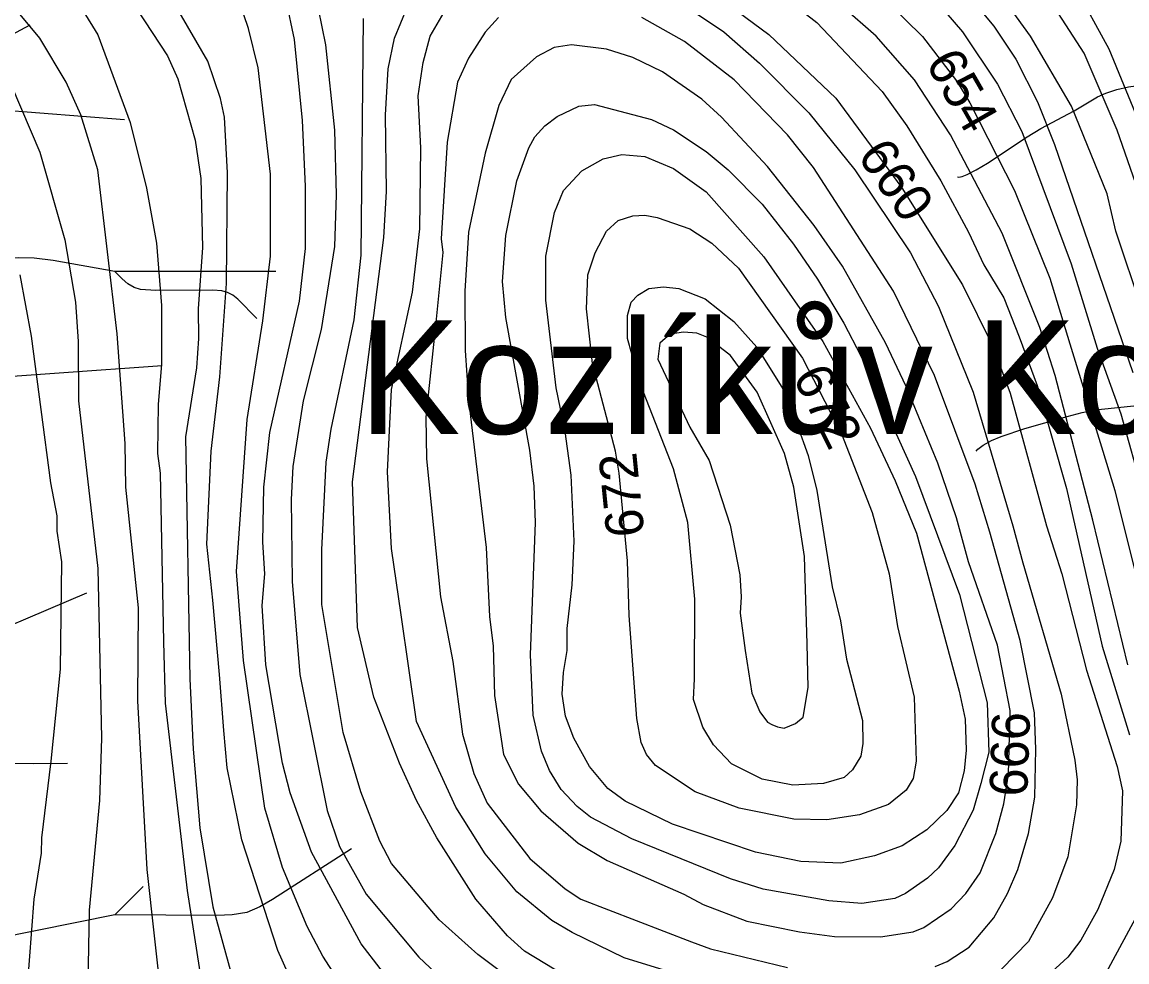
# Model space of a CAD drawing. Extents: x -709584 to -702006, y -1161789 to -1157496.
# Drawn here: x -708051.5 to -707759.7, y -1160434.4 to -1160186.2 of the extents above; entities that cross this region are included whole.
import ezdxf

# ---------------------------------------------------------------- set-up
doc = ezdxf.new("R2010")
doc.units = 0
for name, color, linetype in [('105_místní názvy', 7, 'Continuous'), ('120_vrstevnice hlavní', 7, 'Continuous'), ('121_vrstevnice hlavní_popis', 7, 'Continuous'), ('122_vrstevnice základní', 7, 'Continuous'), ('124_vrstevnice doplňková', 7, 'Continuous'), ('411_akumulovaný odtok', 7, 'Continuous')]:
    doc.layers.add(name, color=color, linetype=linetype)

msp = doc.modelspace()

# ---------------------------------------------------------------- linework, layer by layer
at = {"layer": '120_vrstevnice hlavní'}
for points in [[(-707866.46, -1160180.46), (-707854.31, -1160189.43), (-707836.58, -1160206.29), (-707819.17, -1160229.93), (-707803.11, -1160255.53), (-707795.3, -1160271.44), (-707790.53, -1160284.17), (-707780.98, -1160319.18), (-707776.93, -1160331.9), (-707770.42, -1160357.36), (-707762.32, -1160382.82), (-707760.87, -1160389.18), (-707761.31, -1160402.49), (-707763.04, -1160410.01), (-707767.38, -1160420.57), (-707771.87, -1160428.67), (-707775.34, -1160433.16), (-707782.71, -1160439.95)], [(-707801.66, -1160179.02), (-707794.87, -1160187.26), (-707789.08, -1160195.94), (-707783.29, -1160207.22), (-707778.81, -1160218.5), (-707758.13, -1160278.68)], [(-707968.58, -1160465.84), (-707983.92, -1160431.42), (-707993.46, -1160402.2), (-707997.37, -1160383.11), (-707998.23, -1160373.27), (-707999.39, -1160358.52), (-708001.13, -1160338.85), (-708002.72, -1160324.09), (-708001.56, -1160299.5), (-707999.25, -1160279.83), (-707997.51, -1160255.24), (-707997.22, -1160226.02), (-707998.09, -1160211.27), (-707999.1, -1160206.35), (-708002.43, -1160196.52), (-708010.96, -1160181.76)], [(-707908.12, -1160438.07), (-707918.83, -1160431.56), (-707923.31, -1160427.51), (-707931.7, -1160417.82), (-707941.97, -1160401.62), (-707947.32, -1160391.79), (-707951.81, -1160381.95), (-707958.6, -1160364.45), (-707962.89, -1160346.1), (-707964.24, -1160307.6), (-707956, -1160243.09), (-707955.28, -1160230.94), (-707955.57, -1160210.69), (-707954.84, -1160198.54), (-707953.11, -1160190.44), (-707949.78, -1160182.34)], [(-707887, -1160221.69), (-707879.48, -1160224.87), (-707870.85, -1160231.03), (-707855.62, -1160248.15), (-707840, -1160270.57), (-707827.41, -1160293.43), (-707820.9, -1160307.31), (-707815.26, -1160321.2), (-707803.98, -1160362.86), (-707802.4, -1160370.28), (-707802.21, -1160378.52), (-707802.73, -1160383.92), (-707804.23, -1160389.77), (-707807.26, -1160394.42), (-707812.55, -1160399.56), (-707819.1, -1160403.72), (-707826.41, -1160406.41), (-707835.24, -1160408.36), (-707845.82, -1160407.87), (-707857.79, -1160405.38), (-707879.77, -1160398.01), (-707892.21, -1160391.93), (-707896.84, -1160388.6), (-707901.61, -1160382.82), (-707905.81, -1160375.3), (-707907.98, -1160369.51), (-707908.84, -1160363.73), (-707908.56, -1160357.94), (-707907.54, -1160352.15), (-707907.54, -1160346.37), (-707906.24, -1160334.8), (-707905.66, -1160323.23), (-707906.53, -1160305.87), (-707908.12, -1160294.3), (-707910.44, -1160282.73), (-707913.19, -1160259.58), (-707913.19, -1160248.01), (-707910.87, -1160236.44), (-707908.56, -1160230.65), (-707903.64, -1160225.45), (-707898, -1160222.26), (-707893.08, -1160221.11), (-707887, -1160221.69)], [(-708054.79, -1160476.55), (-708050.16, -1160442.12), (-708048.28, -1160417.82), (-708046.4, -1160405.67), (-708046.26, -1160401.62), (-708043.8, -1160381.37), (-708041.34, -1160357.07), (-708041.05, -1160328.72), (-708042.21, -1160320.62), (-708042.21, -1160316.57), (-708043.94, -1160307.89), (-708049.01, -1160269.13), (-708052.04, -1160252.93)]]:
    msp.add_lwpolyline(points, dxfattribs=at)
at = {"layer": '122_vrstevnice základní'}
for points in [[(-707975.24, -1160173.08), (-707971.33, -1160192.18), (-707969.02, -1160214.74), (-707968.58, -1160231.81), (-707969.02, -1160245.41), (-707972.49, -1160267.39), (-707977.26, -1160286.2)], [(-707857.32, -1160174.06), (-707841.58, -1160186.25), (-707824.37, -1160204.47), (-707817.86, -1160213.58), (-707808.9, -1160228.05), (-707801.52, -1160241.65), (-707797.47, -1160250.32), (-707792.26, -1160259), (-707788.21, -1160269.27), (-707783.44, -1160282.15), (-707775.63, -1160309.34), (-707766.23, -1160351), (-707758.99, -1160374.43)], [(-707759.43, -1160355.92), (-707768.69, -1160317.73), (-707778.67, -1160279.54), (-707782.71, -1160266.81), (-707792.7, -1160241.94), (-707806.29, -1160215.9), (-707815.84, -1160201.44), (-707825.96, -1160189.86), (-707844.04, -1160173.95)], [(-707756.68, -1160230.94), (-707762.32, -1160214.74), (-707770.97, -1160194.33), (-707783.73, -1160174.53)], [(-708038.74, -1160177.71), (-708031.5, -1160189.57), (-708022.97, -1160212.72), (-708018.63, -1160230.07), (-708016.03, -1160244.54), (-708014.73, -1160261.03), (-708014.73, -1160276.65), (-708015.59, -1160287.06), (-708015.74, -1160300.08), (-708015.01, -1160305.29), (-708014.15, -1160349.84), (-708013.71, -1160366.04), (-708007.93, -1160415.51), (-708003.88, -1160441.54)], [(-708025.43, -1160176.27), (-708013.13, -1160195.07), (-708010.39, -1160201.15), (-708005.76, -1160217.35), (-708004.31, -1160227.47), (-708003.88, -1160245.7), (-708005.03, -1160261.9), (-708004.89, -1160269.71), (-708005.47, -1160277.52), (-708008.36, -1160295.74), (-708007.2, -1160359.68), (-708006.33, -1160378.19), (-708004.6, -1160399.02), (-708001.13, -1160419.85), (-707996.07, -1160438.07)], [(-707959.76, -1160451.96), (-707972.06, -1160432.87), (-707976.25, -1160425.05), (-707982.76, -1160409.43), (-707987.39, -1160393.81), (-707993.03, -1160354.76), (-707994.91, -1160331.33), (-707992.02, -1160291.11), (-707987.96, -1160265.08), (-707985.94, -1160248.01), (-707985.94, -1160226.31), (-707989.12, -1160198.25), (-707991.73, -1160187.84), (-707995.2, -1160177.42)], [(-707882.38, -1160177.86), (-707866.18, -1160188.71), (-707856.77, -1160196.97), (-707843.76, -1160210.11), (-707831.6, -1160225.16), (-707816.85, -1160247.14), (-707809.48, -1160261.32), (-707800.36, -1160283.88), (-707789.8, -1160319.18), (-707787.2, -1160329.01), (-707777.07, -1160363.73), (-707773.46, -1160381.08), (-707772.88, -1160386.29), (-707773.02, -1160392.94), (-707775.34, -1160406.69), (-707779.39, -1160417.53), (-707785.69, -1160429.03), (-707792.84, -1160436.34)], [(-707773.6, -1160176.56), (-707764.53, -1160193.19), (-707756.1, -1160213.58), (-707751.33, -1160227.76), (-707742.79, -1160257.56), (-707736.14, -1160285.33), (-707733.83, -1160292.27), (-707713.43, -1160370.67), (-707711.55, -1160382.82), (-707707.65, -1160403.07), (-707706.2, -1160425.34), (-707701.71, -1160449.65)], [(-708053.92, -1160536.58), (-708034.25, -1160530.36), (-708020.66, -1160523.41), (-708013.71, -1160516.61), (-708010.1, -1160511.26), (-708008.07, -1160505.48), (-708007.35, -1160493.91), (-708008.51, -1160479.44), (-708009.66, -1160467.29), (-708014.58, -1160445.02), (-708018.48, -1160410.01), (-708020.95, -1160365.46), (-708020.8, -1160340.87), (-708024.13, -1160309.05), (-708024.27, -1160297.48), (-708026.44, -1160268.55), (-708031.5, -1160225.16), (-708035.99, -1160210.69), (-708039.89, -1160202.01), (-708046.84, -1160190.44), (-708056.82, -1160178.29)], [(-707946.89, -1160449.21), (-707961.93, -1160429.68), (-707975.09, -1160405.38), (-707980.73, -1160389.76), (-707982.76, -1160381.95), (-707987.1, -1160355.92), (-707988.11, -1160340.29), (-707987.39, -1160331.9), (-707987.96, -1160323.52), (-707987.68, -1160309.05), (-707986.08, -1160294.59), (-707978.28, -1160259.87), (-707976.68, -1160245.99), (-707976.68, -1160229.5), (-707977.41, -1160212.14), (-707979.58, -1160190.73), (-707981.75, -1160180.32)], [(-707870.23, -1160440.24), (-707892.5, -1160433.3), (-707906.24, -1160426.65), (-707911.59, -1160423.46), (-707920.85, -1160415.94), (-707929.24, -1160405.82), (-707936.91, -1160393.52), (-707947.35, -1160370.9), (-707951.39, -1160342.77), (-707953.97, -1160325.25), (-707954.99, -1160305), (-707953.98, -1160283.23), (-707948.43, -1160257.54), (-707946.45, -1160240.78), (-707946.16, -1160219.37), (-707946.89, -1160205.63), (-707945.58, -1160196.81), (-707943.7, -1160189.86), (-707938.21, -1160180.32)], [(-707822.78, -1160181.04), (-707813.67, -1160190.01), (-707804.7, -1160201.72), (-707801.23, -1160207.51), (-707789.37, -1160230.65), (-707780.11, -1160253.8), (-707774.76, -1160271.15), (-707766.08, -1160299.5), (-707762.9, -1160309.92), (-707744.09, -1160385.42), (-707743.08, -1160393.23), (-707739.34, -1160424.32), (-707738.45, -1160442.12), (-707740.62, -1160459.48), (-707742.07, -1160466.42), (-707750.46, -1160494.2), (-707751.47, -1160501.14), (-707751.47, -1160511.55), (-707750.03, -1160521.97), (-707747.86, -1160528.91), (-707741.06, -1160539.18), (-707734.11, -1160546.99), (-707722.69, -1160556.25), (-707700.41, -1160569.84)], [(-707809.76, -1160181.04), (-707803.11, -1160188.71), (-707793.85, -1160202.59), (-707787.49, -1160215.03), (-707774.47, -1160250.03), (-707767.53, -1160272.31), (-707761.31, -1160289.67), (-707755.38, -1160310.79)], [(-707755.67, -1160262.19), (-707762.61, -1160241.36), (-707764.92, -1160231.52), (-707774.33, -1160208.38), (-707785.17, -1160189.86), (-707791.83, -1160180.61)], [(-707919.4, -1160441.26), (-707931.12, -1160432.43), (-707941.39, -1160423.32), (-707953.97, -1160408.42), (-707957.01, -1160402.49), (-707962.07, -1160389.47), (-707966.7, -1160373.85), (-707972.34, -1160340), (-707972.34, -1160325.54), (-707971.19, -1160302.4), (-707969.89, -1160293.72), (-707963.81, -1160264.79), (-707961.93, -1160247.72), (-707961.35, -1160185.24)], [(-707925.7, -1160184.98), (-707929.24, -1160188.85), (-707933.58, -1160195.65), (-707936.47, -1160202.01), (-707939.22, -1160217.92)], [(-707810.34, -1160435.61), (-707807.16, -1160434.31), (-707801.38, -1160430.55), (-707794.87, -1160422.74), (-707791.25, -1160416.38), (-707788.5, -1160410.01), (-707785.75, -1160400.47), (-707784.02, -1160390.92), (-707783.73, -1160378.19), (-707784.16, -1160368.64), (-707787.92, -1160349.55), (-707795.88, -1160320.91), (-707799.78, -1160308.18), (-707810.49, -1160279.54), (-707821.33, -1160257.27), (-707842.45, -1160224.58), (-707849.4, -1160215.9), (-707863.43, -1160201.44), (-707876.59, -1160191.31), (-707887.87, -1160184.95)], [(-707914.49, -1160394.53), (-707904.65, -1160403.07), (-707896.99, -1160407.66), (-707876.73, -1160416.52), (-707871.67, -1160419.27), (-707860.1, -1160423.61), (-707846.21, -1160426.5), (-707836.96, -1160427.66), (-707824.81, -1160427.8), (-707816.13, -1160426.5), (-707813.38, -1160425.34), (-707806.15, -1160420.43), (-707802.24, -1160416.38), (-707798.48, -1160410.88), (-707794.29, -1160400.47), (-707792.26, -1160392.66), (-707790.96, -1160384.84), (-707790.56, -1160367.97), (-707793.85, -1160350.71), (-707801.52, -1160328.72), (-707804.7, -1160317.15), (-707809.62, -1160302.69), (-707818.01, -1160282.44), (-707823.51, -1160270.86), (-707834.79, -1160250.61), (-707842.31, -1160239.91), (-707854.6, -1160224.29), (-707866.75, -1160211.27), (-707871.96, -1160206.5), (-707882.38, -1160199.27), (-707890.19, -1160195.5), (-707897.13, -1160193.33), (-707906.39, -1160192.18), (-707911.02, -1160192.9), (-707915.64, -1160195.36), (-707922.3, -1160201.29), (-707925.62, -1160208.23), (-707929.24, -1160220.82), (-707933.58, -1160241.65), (-707934.59, -1160257.27), (-707934.45, -1160272.89), (-707933.58, -1160285.91), (-707928.95, -1160324.96), (-707928.08, -1160343.19), (-707927.07, -1160351), (-707926.78, -1160364.02), (-707924.32, -1160379.64), (-707920.42, -1160387.45), (-707914.49, -1160394.53)], [(-708054.21, -1160203.17), (-708046.84, -1160220.53), (-708040.18, -1160243.67), (-708037.43, -1160260.16), (-708036.71, -1160270.57), (-708036.57, -1160286.2), (-708031.5, -1160330.46), (-708030.49, -1160375.3), (-708031.07, -1160391.79), (-708033.82, -1160420.72), (-708034.11, -1160440.1), (-708033.53, -1160457.17), (-708032.52, -1160468.74), (-708032.52, -1160485.52), (-708036.13, -1160502.58), (-708046.26, -1160514.3), (-708053.06, -1160519.36)], [(-707830.01, -1160274.34), (-707815.55, -1160306.16), (-707803.92, -1160337.39), (-707796.61, -1160366.01), (-707796.2, -1160378.98), (-707798.26, -1160387.26), (-707800.28, -1160394.36), (-707805.14, -1160403.65), (-707809.48, -1160409.58), (-707812.37, -1160412.33), (-707818.15, -1160416.38), (-707821.05, -1160417.68), (-707829.73, -1160418.98), (-707838.4, -1160418.26), (-707855.76, -1160415.22), (-707864.44, -1160412.47), (-707890.48, -1160401.91), (-707901.35, -1160396.16), (-707904.94, -1160393.38), (-707909.13, -1160388.89), (-707912.17, -1160383.83), (-707914.34, -1160378.77), (-707916.51, -1160369.22), (-707917.23, -1160353.31), (-707915.93, -1160318.31), (-707916.22, -1160308.76), (-707917.38, -1160299.21), (-707923.74, -1160264.21), (-707924.61, -1160254.66), (-707923.74, -1160242.51), (-707920.85, -1160228.05), (-707917.67, -1160219.37), (-707916.08, -1160216.48), (-707913.47, -1160213.58), (-707910.15, -1160211.13), (-707904.51, -1160208.38), (-707900.31, -1160207.94), (-707885.27, -1160211.85), (-707879.48, -1160214.6), (-707870.8, -1160220.38), (-707865.02, -1160225.16), (-707856.05, -1160234.27), (-707847.81, -1160244.83), (-707841.44, -1160254.08), (-707834.5, -1160265.66), (-707830.01, -1160274.34)], [(-707939.22, -1160217.92), (-707940.81, -1160243.38), (-707940.37, -1160247.02), (-707942.11, -1160264.64), (-707944.86, -1160290.54), (-707944.72, -1160301.53), (-707940.96, -1160337.98), (-707937.77, -1160355.05), (-707935.17, -1160374.28), (-707932.21, -1160384.67), (-707928.68, -1160392.5), (-707917.38, -1160407.12), (-707908.12, -1160415.07), (-707903.93, -1160417.82), (-707874.71, -1160429.11), (-707869.65, -1160430.99), (-707849.4, -1160435.9)], [(-707822.49, -1160331.9), (-707820.32, -1160345.79), (-707815.9, -1160364.51), (-707815.4, -1160381.39), (-707816.14, -1160385.96), (-707818.01, -1160389.04), (-707822.64, -1160392.8), (-707830.3, -1160395.55), (-707838.98, -1160396.85), (-707847.66, -1160396.71), (-707862.12, -1160393.81), (-707873.7, -1160389.47), (-707884.26, -1160382.53), (-707886.57, -1160379.64), (-707888.02, -1160376.46), (-707889.17, -1160370.09), (-707891.2, -1160342.9), (-707891.63, -1160328.43), (-707893.8, -1160305.29), (-707894.81, -1160299.5), (-707900.89, -1160276.36), (-707902.48, -1160261.9), (-707902.05, -1160252.93), (-707900.17, -1160247.14), (-707897.13, -1160241.36), (-707894.09, -1160238.61), (-707890.19, -1160237.31), (-707887, -1160237.16), (-707883.82, -1160237.74), (-707875.14, -1160240.78), (-707869.36, -1160244.54), (-707862.27, -1160251.19), (-707845.38, -1160274.92), (-707835.08, -1160294.88), (-707826.98, -1160315.7), (-707822.49, -1160331.9)], [(-707871.09, -1160259.29), (-707863.57, -1160265.22), (-707857.48, -1160271.99), (-707849.69, -1160284.46), (-707843.9, -1160300.66), (-707841.58, -1160309.92), (-707837.54, -1160335.38), (-707835.37, -1160344.34), (-707833.78, -1160354.47), (-707829.58, -1160370.67), (-707829.44, -1160376.74), (-707830, -1160380.05), (-707832.18, -1160383.69), (-707834.35, -1160385.71), (-707839.85, -1160387.3), (-707847.95, -1160387.74), (-707856.05, -1160386.15), (-707864.15, -1160382.1), (-707868.92, -1160377.03), (-707871.7, -1160372.39), (-707874.2, -1160365.12), (-707873.96, -1160359.66), (-707873.84, -1160338.56), (-707875.72, -1160318.31), (-707879.48, -1160304.13), (-707888.16, -1160281.86), (-707891.63, -1160269.71), (-707891.63, -1160263.63), (-707890.62, -1160260.16), (-707888.88, -1160258.28), (-707885.99, -1160256.54), (-707882.09, -1160256.11), (-707878.04, -1160256.54), (-707871.09, -1160259.29)], [(-707977.26, -1160286.2), (-707980.01, -1160303.55), (-707980.44, -1160312.23), (-707980.16, -1160333.93), (-707978.13, -1160358.52), (-707970.9, -1160394.39), (-707967.72, -1160403.94), (-707960.63, -1160416.52), (-707946.74, -1160433.16), (-707935.03, -1160444.15)], [(-707757.55, -1160423.03), (-707765.79, -1160438.36)]]:
    msp.add_lwpolyline(points, dxfattribs=at)
at = {"layer": '124_vrstevnice doplňková'}
msp.add_lwpolyline([(-707875.14, -1160293.14), (-707870.08, -1160301.96), (-707864.53, -1160319.09), (-707861.98, -1160332.19), (-707861.55, -1160337.98), (-707861.84, -1160342.32), (-707860.53, -1160352.15), (-707858.8, -1160363.44), (-707856.63, -1160368.35), (-707854.6, -1160371.1), (-707853.45, -1160371.68), (-707852.04, -1160372.32), (-707850.27, -1160372.64), (-707847.28, -1160371.46), (-707845.19, -1160369.72), (-707843.93, -1160361.9), (-707844.19, -1160350.42), (-707844.91, -1160327.28), (-707847.66, -1160309.05), (-707850.12, -1160300.08), (-707857.35, -1160283.88), (-707864.44, -1160274.19), (-707870.65, -1160269.42), (-707873.3, -1160268.35), (-707876.79, -1160268.07), (-707880.32, -1160268.56), (-707883.09, -1160271.01), (-707883.6, -1160275.17), (-707875.14, -1160293.14)], dxfattribs=at)
at = {"layer": '411_akumulovaný odtok'}
for p, q in [((-708049.49, -1160187), (-708086.99, -1160207)), ((-708024.49, -1160212), (-708086.99, -1160207)), ((-707984.49, -1160252), (-708026.99, -1160252)), ((-708019.49, -1160414.5), (-708026.99, -1160422)), ((-708026.99, -1160422), (-708076.99, -1160432))]:
    msp.add_line(p, q, dxfattribs=at)
for points in [[(-707804.49, -1160227), (-707804.1, -1160227.13), (-707803.22, -1160226.94), (-707801.91, -1160226.45), (-707799.5, -1160225.21), (-707796.57, -1160223.43), (-707786.07, -1160216.45), (-707782.44, -1160214.24), (-707773.64, -1160209.61), (-707767.45, -1160205.93), (-707765.29, -1160204.9), (-707762.38, -1160203.94), (-707759.29, -1160203.28), (-707756.07, -1160202.81), (-707742.64, -1160201.63), (-707735.93, -1160200.67), (-707732.66, -1160199.88), (-707729.54, -1160198.81), (-707726.48, -1160197.51), (-707720.5, -1160194.44), (-707714.63, -1160190.99), (-707694.33, -1160178.13)], [(-707799.49, -1160299.5), (-707799.08, -1160298.93), (-707797.69, -1160297.93), (-707795.44, -1160296.69), (-707792.93, -1160295.62), (-707786.69, -1160293.54), (-707775.5, -1160290.3), (-707771.54, -1160289.25), (-707768.08, -1160288.57), (-707752.02, -1160286.89), (-707745.71, -1160285.79), (-707742.65, -1160284.94), (-707739.45, -1160283.71), (-707736.33, -1160282.22), (-707730.24, -1160278.73), (-707721.33, -1160272.84), (-707641.99, -1160217)], [(-708026.99, -1160252), (-708043.29, -1160249.17), (-708048.33, -1160248.56), (-708052.45, -1160248.41), (-708056.4, -1160248.82), (-708062.56, -1160250.65), (-708064.51, -1160251.07), (-708068.57, -1160251.58), (-708077, -1160251.92), (-708094.14, -1160251.96), (-708100.43, -1160252.3), (-708104.44, -1160252.97), (-708106.35, -1160253.54), (-708109.7, -1160255.2), (-708114.85, -1160258.4), (-708116.98, -1160259.46), (-708119.28, -1160260.37), (-708121.82, -1160261.08), (-708124.35, -1160261.57), (-708128.81, -1160262.02), (-708131.99, -1160262)], [(-707989.49, -1160264.5), (-707994.55, -1160259.34), (-707995.88, -1160258.28), (-707997.22, -1160257.56), (-707998.72, -1160257.18), (-708001.14, -1160256.97), (-708016.17, -1160257.04), (-708020.24, -1160256.82), (-708021.91, -1160256.31), (-708023.54, -1160255.29), (-708025.04, -1160254.01), (-708026.99, -1160252)], [(-708014.49, -1160277), (-708069.01, -1160280.84), (-708075.4, -1160281.63), (-708079.47, -1160282.59), (-708081.39, -1160283.31), (-708084.84, -1160285.33), (-708089.59, -1160289.27), (-708095.63, -1160295.19), (-708111.99, -1160312)], [(-708034.49, -1160337), (-708070.9, -1160352.51), (-708075.63, -1160354.3), (-708078.78, -1160355.18), (-708081.92, -1160355.53), (-708083.37, -1160355.41), (-708086.27, -1160354.76), (-708092.17, -1160353.04), (-708097, -1160352.31), (-708104.38, -1160352), (-708116.99, -1160352)], [(-708039.49, -1160382), (-708048.45, -1160382.1), (-708054.87, -1160381.98)], [(-707964.49, -1160404.5), (-707985.35, -1160417.93), (-707988.7, -1160419.85), (-707992.19, -1160421.32), (-707996.04, -1160421.96), (-708000.03, -1160422.12), (-708026.99, -1160422)]]:
    msp.add_lwpolyline(points, dxfattribs=at)

# ---------------------------------------------------------------- texts
at = {"layer": '105_místní názvy'}
msp.add_text('Kozlíkův Kopec', height=30, dxfattribs=at).set_placement((-707962.56, -1160294.93))
at = {"layer": '121_vrstevnice hlavní_popis'}
for s, rotation, p in [('654', 299.9089, (-707813.05, -1160196.95)), ('660', 304.9498, (-707831.12, -1160221.53)), ('672', 296.57, (-707848.11, -1160279.81)), ('672', 95.709, (-707887.11, -1160321.7)), ('666', 87.9787, (-707786.05, -1160390.85))]:
    msp.add_text(s, height=10, rotation=rotation, dxfattribs=at).set_placement(p)

doc.saveas('drawing.dxf')
